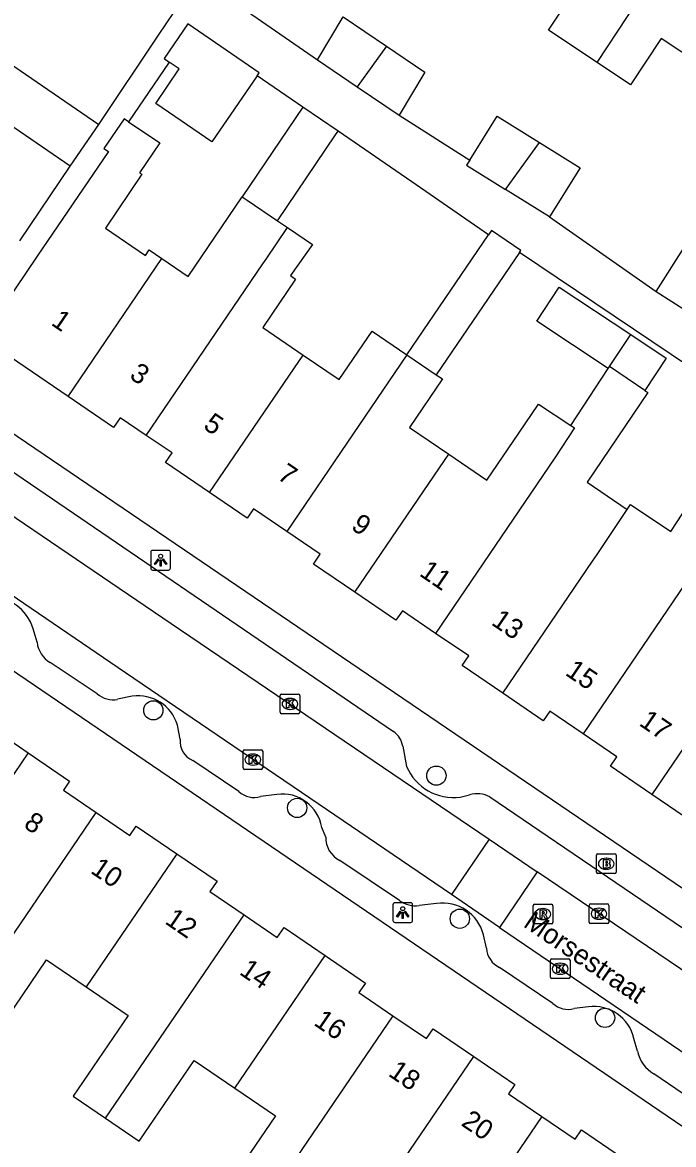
# Model space of a CAD drawing. Extents: x 159280 to 160375, y 384531 to 385872.
# Drawn here: x 159861.5 to 159894.5, y 384790.9 to 384847.8 of the extents above; entities that cross this region are included whole.
import ezdxf

# ---------------------------------------------------------------- set-up
doc = ezdxf.new("R2010")
doc.units = 0
for name, color, linetype in [('IMGEO_Boom', 7, 'Continuous'), ('IMGEO_Brandkraan', 7, 'Continuous'), ('IMGEO_Kolk', 7, 'Continuous'), ('IMGEO_Lichtpunt', 7, 'Continuous'), ('IMGEO_Openbare_ruimte_label', 7, 'Continuous'), ('IMGEO_Pand', 7, 'Continuous'), ('IMGEO_Pand_nummerreeks', 7, 'Continuous'), ('IMGEO_Rijbaan_lokaal_open', 7, 'Continuous'), ('IMGEO_Rioolput', 7, 'Continuous'), ('IMGEO_Voetpad_open', 7, 'Continuous')]:
    doc.layers.add(name, color=color, linetype=linetype)

msp = doc.modelspace()

# ---------------------------------------------------------------- linework, layer by layer
at = {"layer": 'IMGEO_Boom'}
for centre in [(159868.138, 384812.942), (159882.498, 384809.63), (159875.436, 384807.995), (159883.686, 384802.377), (159891.055, 384797.353)]:
    msp.add_circle(centre, 0.489, dxfattribs=at)
at = {"layer": 'IMGEO_Brandkraan'}
for p, q in [((159890.616, 384804.738), (159890.616, 384805.59)), ((159890.691, 384805.664), (159891.543, 384805.664)), ((159891.617, 384805.59), (159891.617, 384804.738)), ((159891.127, 384804.884), (159891.102, 384804.884)), ((159891.104, 384805.444), (159891.129, 384805.444)), ((159891.543, 384804.664), (159890.691, 384804.664))]:
    msp.add_line(p, q, dxfattribs=at)
for points in [[(159890.616, 384804.738), (159890.616, 384805.59)], [(159890.691, 384805.664), (159891.543, 384805.664)], [(159891.617, 384805.59), (159891.617, 384804.738)], [(159890.964, 384805.364), (159890.964, 384804.964), (159891.177, 384804.964)], [(159891.195, 384805.364), (159890.964, 384805.364)], [(159891.143, 384805.283), (159891.089, 384805.283), (159891.089, 384805.207)], [(159891.089, 384805.207), (159891.142, 384805.207)], [(159891.151, 384805.131), (159891.089, 384805.131), (159891.089, 384805.05)], [(159891.089, 384805.05), (159891.151, 384805.05)], [(159891.543, 384804.664), (159890.691, 384804.664)]]:
    msp.add_lwpolyline(points, dxfattribs=at)
for centre, radius, start, end in [((159890.693, 384805.588), 0.0765, 91.552, 178.448), ((159890.693, 384805.588), 0.0765, 91.552, 178.448), ((159891.541, 384805.588), 0.0765, 1.552, 88.448), ((159891.541, 384805.588), 0.0765, 1.552, 88.448), ((159891.144, 384805.245), 0.0379, 267.8285, 90.9355), ((159891.152, 384805.09), 0.0404, 269.8759, 90.5077), ((159891.183, 384805.215), 0.251, 268.6676, 293.5347), ((159891.199, 384805.219), 0.145, 59.4692, 91.5367), ((159891.224, 384805.266), 0.0922, 285.5137, 58.1501), ((159891.229, 384805.074), 0.105, 301.3115, 78.989), ((159890.693, 384804.74), 0.0765, 181.552, 268.448), ((159890.693, 384804.74), 0.0765, 181.552, 268.448), ((159891.541, 384804.74), 0.0765, 271.552, 358.448), ((159891.541, 384804.74), 0.0765, 271.552, 358.448)]:
    msp.add_arc(centre, radius, start, end, dxfattribs=at)
for centre, major_axis, ratio, start_param, end_param in [((159891.103, 384805.164), (-0.387, 0.002), 0.722429, 4.712389, 7.853982), ((159891.128, 384805.164), (-0.39, 0.002), 0.717154, 1.570796, 4.712389)]:
    msp.add_ellipse(centre, major_axis=major_axis, ratio=ratio, start_param=start_param, end_param=end_param, dxfattribs=at)
at = {"layer": 'IMGEO_Kolk'}
for p, q in [((159874.567, 384812.842), (159874.567, 384813.694)), ((159874.642, 384813.768), (159875.494, 384813.768)), ((159875.055, 384813.548), (159875.08, 384813.548)), ((159875.568, 384813.694), (159875.568, 384812.842)), ((159875.078, 384812.988), (159875.053, 384812.988)), ((159875.494, 384812.768), (159874.642, 384812.768)), ((159872.688, 384810.02), (159872.688, 384810.872)), ((159872.763, 384810.946), (159873.615, 384810.946)), ((159873.176, 384810.726), (159873.201, 384810.726)), ((159873.689, 384810.872), (159873.689, 384810.02)), ((159873.199, 384810.166), (159873.174, 384810.166)), ((159873.615, 384809.946), (159872.763, 384809.946)), ((159890.248, 384802.202), (159890.248, 384803.054)), ((159890.323, 384803.128), (159891.175, 384803.128)), ((159890.736, 384802.908), (159890.761, 384802.908)), ((159891.249, 384803.054), (159891.249, 384802.202)), ((159891.175, 384802.128), (159890.323, 384802.128)), ((159890.759, 384802.348), (159890.734, 384802.348)), ((159888.355, 384800.341), (159889.207, 384800.341)), ((159888.28, 384799.415), (159888.28, 384800.267)), ((159888.768, 384800.121), (159888.793, 384800.121)), ((159889.281, 384800.267), (159889.281, 384799.415)), ((159889.207, 384799.341), (159888.355, 384799.341)), ((159888.791, 384799.561), (159888.766, 384799.561))]:
    msp.add_line(p, q, dxfattribs=at)
for points in [[(159874.567, 384812.842), (159874.567, 384813.694)], [(159874.642, 384813.768), (159875.494, 384813.768)], [(159874.888, 384813.468), (159875.011, 384813.468), (159875.011, 384813.317), (159875.141, 384813.468), (159875.305, 384813.468), (159875.159, 384813.317), (159875.312, 384813.068), (159875.16, 384813.068), (159875.075, 384813.232), (159875.011, 384813.165), (159875.011, 384813.068), (159874.888, 384813.068), (159874.888, 384813.468)], [(159875.568, 384813.694), (159875.568, 384812.842)], [(159875.494, 384812.768), (159874.642, 384812.768)], [(159872.688, 384810.02), (159872.688, 384810.872)], [(159872.763, 384810.946), (159873.615, 384810.946)], [(159873.009, 384810.646), (159873.132, 384810.646), (159873.132, 384810.495), (159873.262, 384810.646), (159873.426, 384810.646), (159873.28, 384810.495), (159873.433, 384810.246), (159873.281, 384810.246), (159873.196, 384810.41), (159873.132, 384810.343), (159873.132, 384810.246), (159873.009, 384810.246), (159873.009, 384810.646)], [(159873.689, 384810.872), (159873.689, 384810.02)], [(159873.615, 384809.946), (159872.763, 384809.946)], [(159890.248, 384802.202), (159890.248, 384803.054)], [(159890.323, 384803.128), (159891.175, 384803.128)], [(159890.569, 384802.828), (159890.692, 384802.828), (159890.692, 384802.677), (159890.822, 384802.828), (159890.986, 384802.828), (159890.84, 384802.677), (159890.993, 384802.428), (159890.841, 384802.428), (159890.756, 384802.592), (159890.692, 384802.525), (159890.692, 384802.428), (159890.569, 384802.428), (159890.569, 384802.828)], [(159891.249, 384803.054), (159891.249, 384802.202)], [(159891.175, 384802.128), (159890.323, 384802.128)], [(159888.355, 384800.341), (159889.207, 384800.341)], [(159888.28, 384799.415), (159888.28, 384800.267)], [(159888.601, 384800.041), (159888.724, 384800.041), (159888.724, 384799.89), (159888.854, 384800.041), (159889.018, 384800.041), (159888.872, 384799.89), (159889.025, 384799.641), (159888.873, 384799.641), (159888.788, 384799.805), (159888.724, 384799.738), (159888.724, 384799.641), (159888.601, 384799.641), (159888.601, 384800.041)], [(159889.281, 384800.267), (159889.281, 384799.415)], [(159889.207, 384799.341), (159888.355, 384799.341)]]:
    msp.add_lwpolyline(points, dxfattribs=at)
for centre, start, end in [((159874.644, 384813.692), 91.552, 178.448), ((159874.644, 384813.692), 91.552, 178.448), ((159875.492, 384813.692), 1.552, 88.448), ((159875.492, 384813.692), 1.552, 88.448), ((159874.644, 384812.844), 181.552, 268.448), ((159874.644, 384812.844), 181.552, 268.448), ((159875.492, 384812.844), 271.552, 358.448), ((159875.492, 384812.844), 271.552, 358.448), ((159872.765, 384810.87), 91.552, 178.448), ((159872.765, 384810.87), 91.552, 178.448), ((159873.613, 384810.87), 1.552, 88.448), ((159873.613, 384810.87), 1.552, 88.448), ((159872.765, 384810.022), 181.552, 268.448), ((159872.765, 384810.022), 181.552, 268.448), ((159873.613, 384810.022), 271.552, 358.448), ((159873.613, 384810.022), 271.552, 358.448), ((159890.325, 384803.052), 91.552, 178.448), ((159890.325, 384803.052), 91.552, 178.448), ((159891.173, 384803.052), 1.552, 88.448), ((159891.173, 384803.052), 1.552, 88.448), ((159890.325, 384802.204), 181.552, 268.448), ((159890.325, 384802.204), 181.552, 268.448), ((159891.173, 384802.204), 271.552, 358.448), ((159891.173, 384802.204), 271.552, 358.448), ((159888.357, 384800.265), 91.552, 178.448), ((159888.357, 384800.265), 91.552, 178.448), ((159889.205, 384800.265), 1.552, 88.448), ((159889.205, 384800.265), 1.552, 88.448), ((159888.357, 384799.417), 181.552, 268.448), ((159888.357, 384799.417), 181.552, 268.448), ((159889.205, 384799.417), 271.552, 358.448), ((159889.205, 384799.417), 271.552, 358.448)]:
    msp.add_arc(centre, 0.0765, start, end, dxfattribs=at)
for centre, major_axis, ratio, start_param, end_param in [((159875.054, 384813.268), (-0.387, 0.002), 0.722429, 4.712389, 7.853982), ((159875.079, 384813.268), (-0.39, 0.002), 0.717154, 1.570796, 4.712389), ((159873.175, 384810.446), (-0.387, 0.002), 0.722429, 4.712389, 7.853982), ((159873.2, 384810.446), (-0.39, 0.002), 0.717154, 1.570796, 4.712389), ((159890.735, 384802.628), (-0.387, 0.002), 0.722429, 4.712389, 7.853982), ((159890.76, 384802.628), (-0.39, 0.002), 0.717154, 1.570796, 4.712389), ((159888.767, 384799.841), (-0.387, 0.002), 0.722429, 4.712389, 7.853982), ((159888.792, 384799.841), (-0.39, 0.002), 0.717154, 1.570796, 4.712389)]:
    msp.add_ellipse(centre, major_axis=major_axis, ratio=ratio, start_param=start_param, end_param=end_param, dxfattribs=at)
at = {"layer": 'IMGEO_Lichtpunt'}
for p, q in [((159868.01, 384820.958), (159868.01, 384820.151)), ((159868.01, 384820.958), (159868.01, 384820.151)), ((159868.912, 384821.053), (159868.104, 384821.053)), ((159868.912, 384821.053), (159868.104, 384821.053)), ((159869.006, 384820.151), (159869.006, 384820.958)), ((159869.006, 384820.151), (159869.006, 384820.958)), ((159868.104, 384820.057), (159868.912, 384820.057)), ((159868.104, 384820.057), (159868.912, 384820.057)), ((159881.197, 384803.183), (159880.389, 384803.183)), ((159881.197, 384803.183), (159880.389, 384803.183)), ((159880.295, 384803.088), (159880.295, 384802.281)), ((159880.295, 384803.088), (159880.295, 384802.281)), ((159881.291, 384802.281), (159881.291, 384803.088)), ((159881.291, 384802.281), (159881.291, 384803.088)), ((159880.389, 384802.187), (159881.197, 384802.187)), ((159880.389, 384802.187), (159881.197, 384802.187))]:
    msp.add_line(p, q, dxfattribs=at)
for points in [[(159868.384, 384820.622), (159868.423, 384820.594), (159868.235, 384820.332), (159868.197, 384820.359), (159868.384, 384820.622)], [(159868.486, 384820.574), (159868.533, 384820.574), (159868.533, 384820.252), (159868.486, 384820.252), (159868.486, 384820.574)], [(159868.596, 384820.594), (159868.634, 384820.621), (159868.821, 384820.359), (159868.782, 384820.331), (159868.596, 384820.594)], [(159880.669, 384802.752), (159880.708, 384802.724), (159880.52, 384802.462), (159880.482, 384802.489), (159880.669, 384802.752)], [(159880.771, 384802.704), (159880.818, 384802.704), (159880.818, 384802.382), (159880.771, 384802.382), (159880.771, 384802.704)], [(159880.881, 384802.724), (159880.919, 384802.751), (159881.106, 384802.489), (159881.067, 384802.461), (159880.881, 384802.724)]]:
    msp.add_lwpolyline(points, dxfattribs=at)
for centre in [(159868.509, 384820.756), (159880.794, 384802.886)]:
    msp.add_circle(centre, 0.0994, dxfattribs=at)
for centre, start, end in [((159868.104, 384820.958), 90, 180), ((159868.104, 384820.958), 90, 180), ((159868.912, 384820.958), 0, 90), ((159868.912, 384820.958), 0, 90), ((159868.104, 384820.151), 180, 270), ((159868.104, 384820.151), 180, 270), ((159868.912, 384820.151), 270, 0), ((159868.912, 384820.151), 270, 360), ((159880.389, 384803.088), 90, 180), ((159880.389, 384803.088), 90, 180), ((159881.197, 384803.088), 0, 90), ((159881.197, 384803.088), 0, 90), ((159880.389, 384802.281), 180, 270), ((159880.389, 384802.281), 180, 270), ((159881.197, 384802.281), 270, 0), ((159881.197, 384802.281), 270, 360)]:
    msp.add_arc(centre, 0.0946, start, end, dxfattribs=at)
at = {"layer": 'IMGEO_Pand'}
for points in [[(159890.652, 384845.784), (159892.198, 384848.127), (159896.476, 384854.608)], [(159890.652, 384845.784), (159888.179, 384847.422), (159889.482, 384849.391), (159889.727, 384849.762), (159888.389, 384850.647)], [(159873.41, 384845.12), (159873.514, 384845.271), (159869.894, 384847.753), (159868.685, 384845.99), (159868.941, 384845.815)], [(159876.466, 384845.925), (159877.774, 384848.106), (159879.972, 384846.617)], [(159858.238, 384847.537), (159865.372, 384842.651)], [(159896.007, 384845.613), (159893.903, 384847.006), (159892.349, 384844.66), (159890.652, 384845.784)], [(159879.972, 384846.617), (159878.475, 384844.564)], [(159879.972, 384846.617), (159881.911, 384845.302), (159880.603, 384843.121)], [(159876.466, 384845.925), (159878.475, 384844.564)], [(159863.92, 384840.532), (159856.787, 384845.418)], [(159873.41, 384845.12), (159871.11, 384841.764), (159868.258, 384843.719), (159869.454, 384845.463), (159868.941, 384845.815)], [(159878.475, 384844.564), (159880.603, 384843.121)], [(159875.721, 384843.531), (159872.64, 384838.987)], [(159877.518, 384842.313), (159875.721, 384843.531)], [(159884.192, 384840.845), (159885.576, 384843.07), (159887.724, 384841.734)], [(159866.883, 384842.788), (159866.662, 384842.938), (159865.636, 384841.427), (159865.856, 384841.277), (159862.244, 384835.963), (159859.433, 384831.827)], [(159863.92, 384840.532), (159865.372, 384842.651)], [(159866.883, 384842.788), (159868.468, 384841.712), (159867.441, 384840.2), (159867.559, 384840.12), (159865.707, 384837.396), (159867.743, 384836.012), (159867.93, 384836.287), (159868.571, 384835.851)], [(159874.438, 384837.768), (159877.386, 384842.118), (159877.518, 384842.313)], [(159886.002, 384839.355), (159887.724, 384841.734)], [(159887.724, 384841.734), (159889.788, 384840.45), (159888.241, 384837.963)], [(159884.192, 384840.845), (159884.029, 384840.583), (159886.002, 384839.355)], [(159888.241, 384837.963), (159886.002, 384839.355)], [(159868.571, 384835.851), (159869.901, 384834.947), (159872.64, 384838.987)], [(159872.64, 384838.987), (159872.907, 384838.806), (159874.438, 384837.768)], [(159867.78, 384826.885), (159873.699, 384835.583), (159873.862, 384835.823), (159874.95, 384837.421)], [(159874.95, 384837.421), (159876.215, 384836.564), (159875.093, 384834.986), (159875.356, 384834.807), (159873.686, 384832.35), (159875.74, 384830.954)], [(159874.438, 384837.768), (159874.95, 384837.421)], [(159881.005, 384830.969), (159885.148, 384837.058)], [(159886.708, 384836.156), (159886.778, 384836.259), (159885.292, 384837.269), (159885.148, 384837.058)], [(159893.651, 384834.187), (159895.036, 384836.353), (159897.421, 384834.828), (159896.036, 384832.662)], [(159863.81, 384828.852), (159868.571, 384835.851)], [(159886.708, 384836.156), (159882.491, 384829.959)], [(159891.221, 384830.28), (159887.592, 384832.682), (159888.726, 384834.396), (159892.355, 384831.993)], [(159893.651, 384834.187), (159896.036, 384832.662)], [(159863.81, 384828.852), (159859.433, 384831.827)], [(159875.74, 384830.954), (159877.565, 384829.713), (159879.236, 384832.171), (159881.005, 384830.969)], [(159891.286, 384830.378), (159892.355, 384831.993)], [(159892.355, 384831.993), (159894.152, 384830.804), (159893.069, 384829.166)], [(159870.996, 384823.982), (159875.524, 384830.636), (159875.74, 384830.954)], [(159881.005, 384830.969), (159874.913, 384822.016)], [(159881.005, 384830.969), (159882.491, 384829.959)], [(159882.491, 384829.959), (159882.802, 384829.748), (159881.131, 384827.29), (159883.131, 384825.931)], [(159889.322, 384827.386), (159891.221, 384830.28)], [(159891.221, 384830.28), (159891.286, 384830.378)], [(159893.069, 384829.166), (159891.286, 384830.378)], [(159867.78, 384826.885), (159866.463, 384827.78), (159866.123, 384827.28), (159863.81, 384828.852)], [(159893.069, 384829.166), (159893.232, 384829.055), (159890.141, 384824.506), (159892.175, 384823.123)], [(159883.131, 384825.931), (159885.064, 384824.617), (159886.676, 384826.988), (159887.679, 384828.464), (159889.322, 384827.386)], [(159889.322, 384827.386), (159889.51, 384827.262), (159888.511, 384825.74), (159882.458, 384816.846)], [(159870.996, 384823.982), (159868.763, 384825.5), (159869.096, 384825.99), (159867.78, 384826.885)], [(159878.369, 384818.929), (159882.913, 384825.606), (159883.131, 384825.931)], [(159892.175, 384823.123), (159892.343, 384823.374), (159894.387, 384822.007), (159895.864, 384824.258), (159897.628, 384823.101), (159896.794, 384821.831)], [(159874.913, 384822.016), (159873.222, 384823.166), (159872.898, 384822.689), (159870.996, 384823.982)], [(159885.866, 384813.814), (159890.417, 384820.5), (159890.647, 384820.837), (159892.175, 384823.123)], [(159878.369, 384818.929), (159876.262, 384820.361), (159876.606, 384820.866), (159874.913, 384822.016)], [(159896.794, 384821.831), (159896.035, 384820.715), (159889.939, 384811.756)], [(159882.458, 384816.846), (159880.772, 384817.992), (159880.448, 384817.515), (159878.369, 384818.929)], [(159885.866, 384813.814), (159883.812, 384815.21), (159884.145, 384815.699), (159882.458, 384816.846)], [(159898.193, 384815.669), (159897.979, 384815.354), (159893.434, 384808.676)], [(159889.939, 384811.756), (159888.252, 384812.903), (159887.922, 384812.417), (159885.866, 384813.814)], [(159857.686, 384812.866), (159859.352, 384811.732), (159859.684, 384812.219), (159861.787, 384810.787)], [(159893.434, 384808.676), (159891.329, 384810.106), (159891.657, 384810.588), (159889.939, 384811.756)], [(159861.787, 384810.787), (159857.182, 384804.026)], [(159861.787, 384810.787), (159863.892, 384809.354), (159863.576, 384808.889), (159865.24, 384807.756)], [(159897.464, 384806.614), (159895.813, 384807.736), (159895.498, 384807.273), (159893.434, 384808.676)], [(159858.125, 384797.31), (159865.24, 384807.756)], [(159865.24, 384807.756), (159866.94, 384806.598), (159867.266, 384807.076), (159869.335, 384805.667)], [(159869.335, 384805.667), (159864.738, 384798.918)], [(159869.335, 384805.667), (159871.372, 384804.279), (159871.013, 384803.752), (159872.744, 384802.573)], [(159865.719, 384792.257), (159872.744, 384802.573)], [(159872.744, 384802.573), (159874.429, 384801.426), (159874.768, 384801.924), (159876.853, 384800.504)], [(159872.274, 384793.782), (159876.853, 384800.504)], [(159876.853, 384800.504), (159878.898, 384799.112), (159878.571, 384798.632), (159880.295, 384797.458)], [(159858.125, 384797.31), (159859.882, 384796.114), (159862.724, 384800.289), (159864.738, 384798.918)], [(159864.738, 384798.918), (159866.866, 384797.469), (159864.078, 384793.375), (159865.719, 384792.257)], [(159880.295, 384797.458), (159873.225, 384787.078)], [(159880.295, 384797.458), (159881.995, 384796.3), (159882.33, 384796.792), (159884.398, 384795.384)], [(159878.115, 384786.14), (159879.822, 384788.664), (159884.398, 384795.384)], [(159884.398, 384795.384), (159886.472, 384793.971), (159886.152, 384793.501), (159887.847, 384792.347)], [(159865.719, 384792.257), (159867.425, 384791.096), (159870.211, 384795.187), (159872.274, 384793.782)], [(159872.274, 384793.782), (159874.333, 384792.38), (159871.515, 384788.242)], [(159887.847, 384792.347), (159880.797, 384781.995)], [(159887.847, 384792.347), (159889.535, 384791.197), (159889.859, 384791.672), (159891.94, 384790.255)]]:
    msp.add_lwpolyline(points, dxfattribs=at)
at = {"layer": 'IMGEO_Rijbaan_lokaal_open'}
for points in [[(159841.061, 384836.342), (159869.05, 384817.352), (159885.17, 384806.406)], [(159883.263, 384803.596), (159866.73, 384814.841), (159839.216, 384833.593)], [(159885.17, 384806.406), (159883.263, 384803.596)], [(159885.17, 384806.406), (159887.611, 384804.749)], [(159887.611, 384804.749), (159885.702, 384801.937)], [(159945.396, 384765.37), (159926.959, 384778.09), (159908.324, 384790.738), (159887.611, 384804.749)], [(159885.702, 384801.937), (159883.263, 384803.596)], [(159885.702, 384801.937), (159896.121, 384794.85), (159926.868, 384773.971), (159943.479, 384762.606)]]:
    msp.add_lwpolyline(points, dxfattribs=at)
at = {"layer": 'IMGEO_Rioolput'}
for p, q in [((159887.407, 384802.184), (159887.407, 384803.036)), ((159887.482, 384803.11), (159888.334, 384803.11)), ((159887.895, 384802.89), (159887.92, 384802.89)), ((159888.408, 384803.036), (159888.408, 384802.184)), ((159888.334, 384802.11), (159887.482, 384802.11)), ((159887.918, 384802.33), (159887.893, 384802.33))]:
    msp.add_line(p, q, dxfattribs=at)
for points in [[(159887.407, 384802.184), (159887.407, 384803.036)], [(159887.482, 384803.11), (159888.334, 384803.11)], [(159887.996, 384802.808), (159887.744, 384802.81), (159887.744, 384802.41)], [(159887.922, 384802.729), (159887.868, 384802.729), (159887.868, 384802.648)], [(159887.868, 384802.648), (159887.92, 384802.648)], [(159888.408, 384803.036), (159888.408, 384802.184)], [(159888.334, 384802.11), (159887.482, 384802.11)], [(159887.744, 384802.41), (159887.868, 384802.41), (159887.868, 384802.572), (159887.879, 384802.572)], [(159887.926, 384802.543), (159887.997, 384802.41), (159888.137, 384802.41), (159888.072, 384802.536)]]:
    msp.add_lwpolyline(points, dxfattribs=at)
for centre, radius, start, end in [((159887.484, 384803.034), 0.0765, 91.552, 178.448), ((159887.484, 384803.034), 0.0765, 91.552, 178.448), ((159887.904, 384802.837), 0.19, 274.7715, 282.9687), ((159887.928, 384802.633), 0.0964, 77.0061, 93.1865), ((159887.942, 384802.69), 0.0378, 276.6634, 79.6772), ((159887.995, 384802.698), 0.109, 350.3612, 89.416), ((159887.993, 384802.698), 0.112, 277.5842, 350.9817), ((159888.332, 384803.034), 0.0765, 1.552, 88.448), ((159888.332, 384803.034), 0.0765, 1.552, 88.448), ((159887.484, 384802.186), 0.0765, 181.552, 268.448), ((159887.484, 384802.186), 0.0765, 181.552, 268.448), ((159887.878, 384802.519), 0.0533, 26.0293, 88.6989), ((159887.977, 384802.483), 0.108, 29.5134, 73.7905), ((159888.332, 384802.186), 0.0765, 271.552, 358.448), ((159888.332, 384802.186), 0.0765, 271.552, 358.448)]:
    msp.add_arc(centre, radius, start, end, dxfattribs=at)
for centre, major_axis, ratio, start_param, end_param in [((159887.894, 384802.61), (-0.387, 0.002), 0.722429, 4.712389, 7.853982), ((159887.919, 384802.61), (-0.39, 0.002), 0.717154, 1.570796, 4.712389)]:
    msp.add_ellipse(centre, major_axis=major_axis, ratio=ratio, start_param=start_param, end_param=end_param, dxfattribs=at)
at = {"layer": 'IMGEO_Voetpad_open'}
for points in [[(159865.372, 384842.651), (159868.395, 384847.18), (159870.352, 384850.069)], [(159872.912, 384848.382), (159876.466, 384845.925)], [(159868.941, 384845.815), (159866.883, 384842.788)], [(159875.721, 384843.531), (159873.41, 384845.12)], [(159880.603, 384843.121), (159884.192, 384840.845)], [(159885.148, 384837.058), (159881.255, 384839.739), (159877.518, 384842.313)], [(159861.363, 384836.746), (159863.92, 384840.532)], [(159888.241, 384837.963), (159893.651, 384834.187)], [(159904.008, 384824.524), (159886.708, 384836.156)], [(159857.677, 384829.243), (159933.27, 384777.928)], [(159859.008, 384826.382), (159880.327, 384811.876)], [(159927.578, 384769.66), (159852.026, 384821.042)], [(159862.245, 384816.391), (159862.045, 384817.075)], [(159865.291, 384813.778), (159862.907, 384815.372)], [(159867.07, 384813.663), (159866.323, 384813.5)], [(159869.5, 384811.486), (159869.363, 384812.196)], [(159880.796, 384811.121), (159880.985, 384810.1)], [(159872.483, 384808.821), (159870.137, 384810.402)], [(159874.403, 384808.682), (159873.579, 384808.57)], [(159883.713, 384808.543), (159884.181, 384808.664)], [(159885.211, 384808.551), (159918.388, 384786.002)], [(159876.884, 384806.519), (159876.686, 384806.999)], [(159880.623, 384803.306), (159877.598, 384805.335)], [(159882.505, 384803.154), (159881.63, 384803.04)], [(159885.038, 384800.876), (159884.889, 384801.56)], [(159888.404, 384798.077), (159885.699, 384799.907)], [(159890.209, 384797.911), (159889.487, 384797.825)], [(159892.704, 384795.659), (159892.517, 384796.304)], [(159901.391, 384789.147), (159893.533, 384794.514)]]:
    msp.add_lwpolyline(points, dxfattribs=at)
for centre, radius, start, end in [((159859.895, 384816.427), 2.246, 16.7688, 93.3618), ((159863.571, 384816.528), 1.334, 185.9051, 240.115), ((159866.09, 384814.689), 1.212, 228.757, 281.0901), ((159867.357, 384811.586), 2.097, 16.9232, 97.8568), ((159879.592, 384810.896), 1.225, 10.5702, 53.1262), ((159870.521, 384811.357), 1.029, 172.7943, 248.086), ((159883.367, 384811.106), 2.586, 202.8873, 277.6818), ((159873.254, 384809.67), 1.147, 227.7469, 286.4548), ((159874.671, 384806.656), 2.044, 9.6619, 97.5438), ((159884.557, 384807.338), 1.378, 61.6553, 105.8231), ((159878.161, 384806.482), 1.277, 178.328, 243.8554), ((159881.459, 384804.432), 1.402, 233.4008, 277.0056), ((159882.805, 384801.023), 2.152, 14.4562, 98.0085), ((159886.188, 384800.95), 1.152, 183.6976, 244.9018), ((159889.169, 384798.912), 1.132, 227.4929, 286.3093), ((159890.474, 384795.831), 2.097, 13.04, 97.2631), ((159894.371, 384795.993), 1.7, 191.3347, 240.4757)]:
    msp.add_arc(centre, radius, start, end, dxfattribs=at)

# ---------------------------------------------------------------- texts
at = {"layer": 'IMGEO_Openbare_ruimte_label'}
msp.add_text('Morsestraat', height=1, rotation=325.8014, dxfattribs=at).set_placement((159886.856, 384802.01))
at = {"layer": 'IMGEO_Pand_nummerreeks'}
for s, rotation, p in [('1', 325.7944, (159862.903, 384832.515)), ('3', 325.76, (159866.875, 384829.815)), ('5', 325.76, (159870.623, 384827.264)), ('7', 325.759, (159874.372, 384824.712)), ('9', 325.76, (159878.12, 384822.161)), ('11', 325.76, (159881.582, 384819.804)), ('13', 325.76, (159885.236, 384817.317)), ('15', 325.76, (159888.985, 384814.766)), ('17', 325.759, (159892.733, 384812.214)), ('8', 325.7429, (159861.507, 384807.044)), ('10', 325.7429, (159864.902, 384804.732)), ('12', 325.7429, (159868.673, 384802.165)), ('14', 325.7429, (159872.451, 384799.591)), ('16', 325.7429, (159876.227, 384797.02)), ('18', 325.7429, (159880.006, 384794.446)), ('20', 325.7429, (159883.706, 384791.926))]:
    msp.add_text(s, height=1, rotation=rotation, dxfattribs=at).set_placement(p)

doc.saveas('drawing.dxf')
